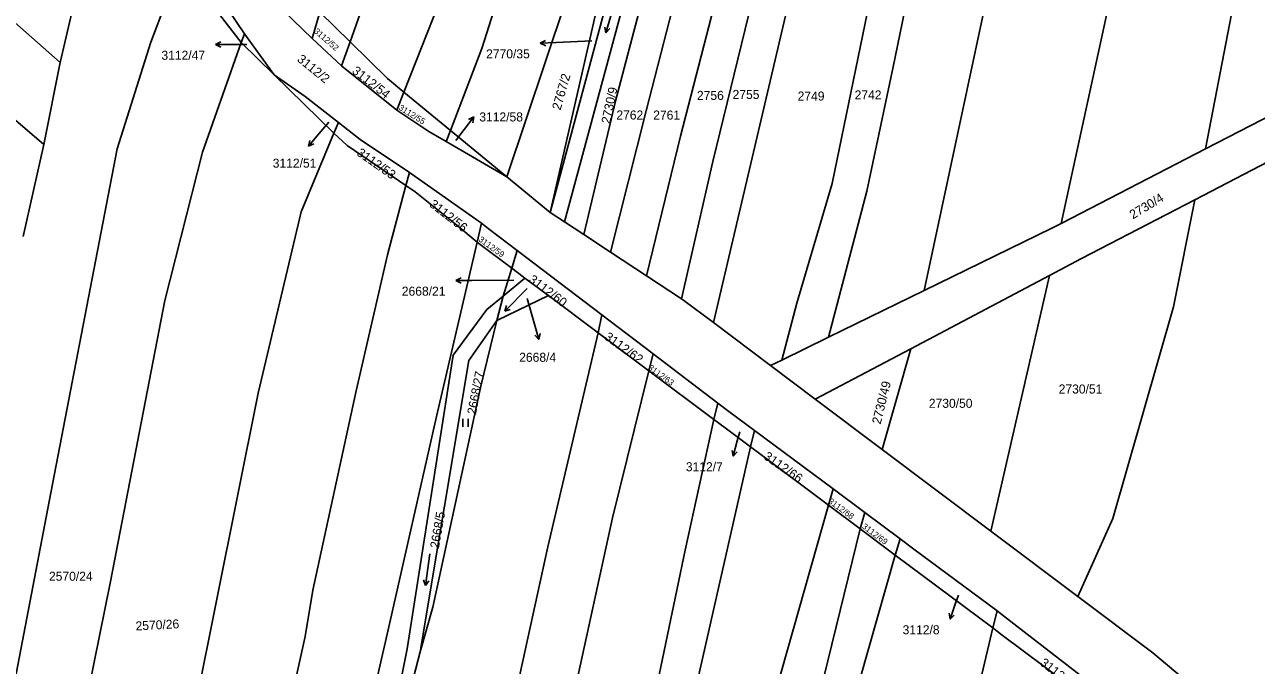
# Model space of a CAD drawing. Extents: x -776734 to -748832, y -1118122 to -976986.
# Drawn here: x -753866 to -753634.1, y -1115185.5 to -1115064.9 of the extents above; entities that cross this region are included whole.
import ezdxf

# ---------------------------------------------------------------- set-up
doc = ezdxf.new("R2010")
doc.units = 0
for name, color, linetype in [('KM_Hranice parcel', 7, 'Continuous'), ('KM_Parcelní čísla', 7, 'Continuous'), ('KM_Pop  PČ popisy', 7, 'Continuous'), ('KM_Značky kultur', 7, 'Continuous')]:
    doc.layers.add(name, color=color, linetype=linetype)

msp = doc.modelspace()

# ---------------------------------------------------------------- linework, layer by layer
at = {"layer": 'KM_Hranice parcel'}
for p, q in [((-753835.51, -1115050.38), (-753824.6, -1115066.64)), ((-753859.25, -1115072.07), (-753855.1, -1115054.13)), ((-753764.22, -1115060.84), (-753775.17, -1115093.59)), ((-753767.01, -1115100.3), (-753757.9, -1115060.21)), ((-753811.82, -1115067.51), (-753817.24, -1115062.32)), ((-753811.82, -1115067.51), (-753810.37, -1115062.57)), ((-753810.37, -1115062.57), (-753804.69, -1115068.16)), ((-753825.23, -1115068.3), (-753824.6, -1115066.64)), ((-753824.6, -1115066.64), (-753819, -1115074.39)), ((-753806.29, -1115072.69), (-753811.82, -1115067.51)), ((-753819, -1115074.39), (-753825.23, -1115068.3)), ((-753806.29, -1115072.69), (-753804.69, -1115068.16)), ((-753607.2, -1115069.43), (-753643.69, -1115088.29)), ((-753862.33, -1115087.47), (-753859.25, -1115072.07)), ((-753807.76, -1115085.35), (-753819, -1115074.39)), ((-753795.93, -1115081), (-753806.29, -1115072.69)), ((-753645.7, -1115097.86), (-753603.38, -1115075.89)), ((-753795.93, -1115081), (-753794.59, -1115077.61)), ((-753794.59, -1115077.61), (-753785.83, -1115084.82)), ((-753807.76, -1115085.35), (-753806.88, -1115083.36)), ((-753786.63, -1115086.91), (-753785.83, -1115084.82)), ((-753785.83, -1115084.82), (-753775.17, -1115093.59)), ((-753866.24, -1115104.81), (-753862.33, -1115087.47)), ((-753775.17, -1115093.59), (-753786.63, -1115086.91)), ((-753643.69, -1115088.29), (-753670.83, -1115102.32)), ((-753794.18, -1115095.22), (-753793.53, -1115092.76)), ((-753793.53, -1115092.76), (-753779.95, -1115102.31)), ((-753792.48, -1115096.38), (-753794.18, -1115095.22)), ((-753767.01, -1115100.3), (-753775.17, -1115093.59)), ((-753784.61, -1115102.63), (-753792.48, -1115096.38)), ((-753767.01, -1115100.3), (-753764.36, -1115102.04)), ((-753780.79, -1115105.85), (-753784.61, -1115102.63)), ((-753780.79, -1115105.85), (-753779.95, -1115102.31)), ((-753760.72, -1115104.43), (-753764.36, -1115102.04)), ((-753755.69, -1115107.74), (-753760.72, -1115104.43)), ((-753780.46, -1115106.13), (-753780.79, -1115105.85)), ((-753774.28, -1115110.75), (-753780.46, -1115106.13)), ((-753774.28, -1115110.75), (-753773.27, -1115107.43)), ((-753773.27, -1115107.43), (-753757.29, -1115119.56)), ((-753748.89, -1115112.2), (-753755.69, -1115107.74)), ((-753775.87, -1115116), (-753774.28, -1115110.75)), ((-753771.78, -1115112.62), (-753775.87, -1115116)), ((-753767.37, -1115115.92), (-753771.78, -1115112.62)), ((-753742.3, -1115116.53), (-753748.89, -1115112.2)), ((-753699.18, -1115125.92), (-753673.06, -1115112.13)), ((-753684.07, -1115160.26), (-753673.06, -1115112.13)), ((-753777.06, -1115120.59), (-753767.37, -1115115.92)), ((-753775.87, -1115116), (-753777.06, -1115120.59)), ((-753758.02, -1115122.91), (-753767.37, -1115115.92)), ((-753714.63, -1115123.75), (-753696.62, -1115114.96)), ((-753758.02, -1115122.91), (-753757.29, -1115119.56)), ((-753757.29, -1115119.56), (-753747.63, -1115126.9)), ((-753725.55, -1115129.08), (-753736.31, -1115120.99)), ((-753748.44, -1115130.08), (-753758.02, -1115122.91)), ((-753714.63, -1115123.75), (-753723.41, -1115128.04)), ((-753699.18, -1115125.92), (-753717.13, -1115135.41)), ((-753704.57, -1115144.86), (-753699.18, -1115125.92)), ((-753748.44, -1115130.08), (-753747.63, -1115126.9)), ((-753747.63, -1115126.9), (-753735.47, -1115136.14)), ((-753723.41, -1115128.04), (-753725.55, -1115129.08)), ((-753736.23, -1115139.2), (-753748.44, -1115130.08)), ((-753725.55, -1115129.08), (-753717.13, -1115135.41)), ((-753735.47, -1115136.14), (-753736.23, -1115139.2)), ((-753735.47, -1115136.14), (-753733.4, -1115137.71)), ((-753704.57, -1115144.86), (-753717.13, -1115135.41)), ((-753736.23, -1115139.2), (-753734.12, -1115140.78)), ((-753733.4, -1115137.71), (-753728.55, -1115141.32)), ((-753734.12, -1115140.78), (-753729.32, -1115144.37)), ((-753729.32, -1115144.37), (-753728.55, -1115141.32)), ((-753684.07, -1115160.26), (-753704.57, -1115144.86)), ((-753714.65, -1115155.34), (-753713.79, -1115152.29)), ((-753713.79, -1115152.29), (-753707.79, -1115156.75)), ((-753708.66, -1115159.82), (-753714.65, -1115155.34)), ((-753708.66, -1115159.82), (-753707.79, -1115156.75)), ((-753707.79, -1115156.75), (-753701.17, -1115161.67)), ((-753702.08, -1115164.74), (-753708.66, -1115159.82)), ((-753667.69, -1115172.56), (-753684.07, -1115160.26)), ((-753701.17, -1115161.67), (-753702.08, -1115164.74)), ((-753701.17, -1115161.67), (-753698.57, -1115163.61)), ((-753702.08, -1115164.74), (-753699.38, -1115166.76)), ((-753698.57, -1115163.61), (-753682.93, -1115175.26)), ((-753699.38, -1115166.76), (-753683.72, -1115178.46)), ((-753683.72, -1115178.46), (-753682.93, -1115175.26)), ((-753792.82, -1115188.05), (-753791.53, -1115182.96))]:
    msp.add_line(p, q, dxfattribs=at)
for points in [[(-753794.59, -1115077.61), (-753787.93, -1115060.8), (-753777.91, -1115023.56), (-753764.5, -1114964.39), (-753747.45, -1114890.29), (-753735.04, -1114826.44), (-753725.78, -1114788.24), (-753719.01, -1114758.28), (-753706.47, -1114700.23), (-753694.32, -1114647.7), (-753687.72, -1114622.89), (-753664.72, -1114512.91)], [(-753744.88, -1114812.91), (-753755.85, -1114860.59), (-753768.37, -1114915.99), (-753784.17, -1114987.23), (-753793.11, -1115028.22), (-753799.33, -1115052.95), (-753804.69, -1115068.16)], [(-754067.98, -1114882.52), (-754045.71, -1114907.17), (-754004.24, -1114946.2), (-753952.66, -1114990.3), (-753910.37, -1115026.73), (-753875.85, -1115057.43), (-753859.25, -1115072.07)], [(-754071.13, -1114898.39), (-754049.63, -1114922.2), (-754022.66, -1114947.85), (-753952.63, -1115010.37), (-753898.79, -1115056.16), (-753862.33, -1115087.47)], [(-753785.83, -1115084.82), (-753779.91, -1115069.41), (-753771.27, -1115042.16), (-753765.37, -1115019.27), (-753758.96, -1114991.55), (-753748.31, -1114942.85)], [(-753670.83, -1115102.32), (-753662.8, -1115065.45), (-753655.03, -1115029.36), (-753643.9, -1114977.12)], [(-753619.54, -1114977.59), (-753625.43, -1114999.63), (-753637.42, -1115055.73), (-753643.69, -1115088.29)], [(-753696.62, -1115114.96), (-753683.7, -1115054.43), (-753667.69, -1114984.06)], [(-753727.25, -1115015.85), (-753732.26, -1115046.29), (-753742.51, -1115085.92), (-753748.89, -1115112.2)], [(-753730.97, -1115018.56), (-753736.42, -1115049.25), (-753741.79, -1115053.28), (-753748.97, -1115081.15), (-753755.69, -1115107.74)], [(-753764.36, -1115102.04), (-753753.61, -1115062.35), (-753744.4, -1115028.3), (-753743.32, -1115027.52)], [(-753760.72, -1115104.43), (-753754.71, -1115079.05), (-753749.42, -1115058.99), (-753743.32, -1115027.52)], [(-753699.56, -1115028.45), (-753704.22, -1115047.53), (-753713.98, -1115094.82), (-753720.64, -1115117.31), (-753723.41, -1115128.04)], [(-753693.08, -1115027.16), (-753702.48, -1115072.87), (-753707.46, -1115096.26), (-753714.63, -1115123.75)], [(-753715.37, -1115032.61), (-753722.47, -1115062.21), (-753736.31, -1115120.99)], [(-753723.63, -1115038.25), (-753736.39, -1115090.66), (-753742.3, -1115116.53)], [(-753889.22, -1115281.32), (-753884.22, -1115266.45), (-753874.89, -1115225.11), (-753861.01, -1115153.01), (-753848.53, -1115088.3), (-753842.2, -1115068.25), (-753836.55, -1115053.32)], [(-753825.23, -1115068.3), (-753834.4, -1115056.28), (-753836.55, -1115053.32)], [(-753756.2, -1115059.98), (-753756.93, -1115062.71), (-753767.01, -1115100.3)], [(-753877.5, -1115290.9), (-753872.01, -1115276.25), (-753867.16, -1115255.51), (-753849.81, -1115169.74), (-753839.59, -1115116.86), (-753832.48, -1115088.95), (-753825.23, -1115068.3)], [(-753804.69, -1115068.16), (-753797.69, -1115075.06), (-753794.59, -1115077.61)], [(-753819, -1115074.39), (-753813.17, -1115078.44), (-753806.88, -1115083.36)], [(-753786.63, -1115086.91), (-753789.87, -1115085.04), (-753795.93, -1115081)], [(-753806.88, -1115083.36), (-753802.83, -1115086.53), (-753793.53, -1115092.76)], [(-753858.9, -1115308.17), (-753841.51, -1115231.47), (-753822.03, -1115134.25), (-753813.93, -1115100.17), (-753807.76, -1115085.35)], [(-753794.18, -1115095.22), (-753805.25, -1115087.66), (-753807.76, -1115085.35)], [(-753847.38, -1115317.7), (-753839.5, -1115293.67), (-753835.79, -1115283.35), (-753829.38, -1115253.16), (-753813.14, -1115180.08), (-753811.71, -1115171.33), (-753803.55, -1115133.82), (-753797.64, -1115108.22), (-753794.18, -1115095.22)], [(-753673.06, -1115112.13), (-753667.05, -1115108.95), (-753645.7, -1115097.86)], [(-753645.7, -1115097.86), (-753649.71, -1115118.04), (-753661.1, -1115157.84), (-753667.69, -1115172.56)], [(-753779.95, -1115102.31), (-753778.72, -1115103.29), (-753773.27, -1115107.43)], [(-753670.83, -1115102.32), (-753672.59, -1115103.23), (-753696.62, -1115114.96)], [(-753835, -1115324.01), (-753823.86, -1115291.7), (-753817.46, -1115264.86), (-753807.73, -1115223.09), (-753797.54, -1115178.81), (-753788.44, -1115138.67), (-753780.79, -1115105.85)], [(-753771.78, -1115112.62), (-753772.1, -1115112.38), (-753774.28, -1115110.75)], [(-753775.87, -1115116), (-753778.95, -1115118.54), (-753785.28, -1115127.14), (-753793.95, -1115182.36), (-753795.04, -1115187.69), (-753798.54, -1115214.71)], [(-753736.31, -1115120.99), (-753741.85, -1115116.83), (-753742.3, -1115116.53)], [(-753791.53, -1115182.96), (-753782.38, -1115128.15), (-753777.06, -1115120.59)], [(-753791.53, -1115182.96), (-753789.1, -1115174.54), (-753780.09, -1115132.96), (-753777.06, -1115120.59)], [(-753758.02, -1115122.91), (-753767.5, -1115163.21), (-753775.58, -1115200.14), (-753786.55, -1115251.31), (-753798.09, -1115295.51)], [(-753789.77, -1115308.69), (-753779.04, -1115265.51), (-753765.42, -1115203.94), (-753755.29, -1115157.75), (-753748.44, -1115130.08)], [(-753776.81, -1115332.22), (-753770.23, -1115300.11), (-753762.92, -1115265.2), (-753759.22, -1115246.04), (-753751.08, -1115209.25), (-753741.66, -1115163.79), (-753736.23, -1115139.2)], [(-753728.55, -1115141.32), (-753726.86, -1115142.58), (-753713.79, -1115152.29)], [(-753773.54, -1115339.7), (-753767.38, -1115311.34), (-753760.97, -1115283.14), (-753750.71, -1115240.6), (-753738.95, -1115186.68), (-753729.32, -1115144.37)], [(-753714.65, -1115155.34), (-753727.64, -1115145.63), (-753729.32, -1115144.37)], [(-753763.66, -1115349.76), (-753755.73, -1115322.54), (-753747.14, -1115288.61), (-753733.22, -1115227.13), (-753724.6, -1115190.55), (-753714.65, -1115155.34)], [(-753759.06, -1115352.33), (-753746.83, -1115314.09), (-753739.87, -1115287.41), (-753725.63, -1115228.17), (-753718.54, -1115199.99), (-753708.66, -1115159.82)], [(-753752.14, -1115356.18), (-753741.33, -1115319.81), (-753726.82, -1115261.41), (-753708.77, -1115188.16), (-753702.08, -1115164.74)], [(-753667.69, -1115172.56), (-753653.62, -1115183.13), (-753638.63, -1115195.73), (-753623.19, -1115211.62), (-753622.14, -1115213.44)], [(-753682.93, -1115175.26), (-753681.13, -1115176.6), (-753661.17, -1115192.03)], [(-753729.17, -1115366.77), (-753720.7, -1115331.7), (-753704.97, -1115267.86), (-753693.75, -1115221.04), (-753683.72, -1115178.46)], [(-753662.43, -1115194.39), (-753681.93, -1115179.8), (-753683.72, -1115178.46)]]:
    msp.add_lwpolyline(points, dxfattribs=at)
at = {"layer": 'KM_Pop  PČ popisy'}
for p, q in [((-753768.897, -1115068.437), (-753767.923, -1115067.885)), ((-753759.18, -1115067.96), (-753765.9, -1115068.28)), ((-753830.021, -1115068.67), (-753829.02, -1115068.169)), ((-753827.02, -1115068.67), (-753830.021, -1115068.67)), ((-753830.021, -1115068.67), (-753829.02, -1115069.171)), ((-753824.13, -1115068.66), (-753827.02, -1115068.67)), ((-753765.9, -1115068.28), (-753768.897, -1115068.437)), ((-753768.897, -1115068.437), (-753767.871, -1115068.885)), ((-753808.72, -1115083.25), (-753810.61, -1115085.49)), ((-753783.21, -1115084.67), (-753781.404, -1115082.273)), ((-753781.404, -1115082.273), (-753782.407, -1115082.772)), ((-753781.404, -1115082.273), (-753781.607, -1115083.374)), ((-753810.61, -1115085.49), (-753812.539, -1115087.789)), ((-753784.8, -1115086.75), (-753783.21, -1115084.67)), ((-753812.539, -1115087.789), (-753812.279, -1115086.7)), ((-753812.539, -1115087.789), (-753811.512, -1115087.344)), ((-753784.771, -1115113.06), (-753783.77, -1115112.559)), ((-753781.77, -1115113.06), (-753784.771, -1115113.06)), ((-753784.771, -1115113.06), (-753783.77, -1115113.561)), ((-753773.88, -1115113.01), (-753781.77, -1115113.06)), ((-753771.37, -1115116.47), (-753769.97, -1115121.29)), ((-753769.97, -1115121.29), (-753769.143, -1115124.175)), ((-753769.143, -1115124.175), (-753769.9, -1115123.35)), ((-753769.143, -1115124.175), (-753768.938, -1115123.074)), ((-753731.35, -1115141.56), (-753731.81, -1115143.23)), ((-753731.81, -1115143.23), (-753732.587, -1115146.129)), ((-753732.587, -1115146.129), (-753732.811, -1115145.032)), ((-753732.587, -1115146.129), (-753731.844, -1115145.291)), ((-753690.2, -1115172.27), (-753690.8, -1115173.97)), ((-753690.8, -1115173.97), (-753691.777, -1115176.807)), ((-753691.777, -1115176.807), (-753691.924, -1115175.698)), ((-753691.777, -1115176.807), (-753690.978, -1115176.024))]:
    msp.add_line(p, q, dxfattribs=at)
at = {"layer": 'KM_Značky kultur'}
for p, q in [((-753754.896, -1115060.69), (-753756.55, -1115066.458)), ((-753756.55, -1115066.458), (-753756.763, -1115065.38)), ((-753756.55, -1115066.458), (-753755.799, -1115065.657)), ((-753771.347, -1115114.595), (-753775.589, -1115118.837)), ((-753775.589, -1115118.837), (-753775.253, -1115117.792)), ((-753775.589, -1115118.837), (-753774.544, -1115118.501)), ((-753783.481, -1115140.61), (-753783.481, -1115139.11)), ((-753782.48, -1115140.61), (-753782.48, -1115139.11)), ((-753789.663, -1115164.515), (-753790.498, -1115170.457)), ((-753790.498, -1115170.457), (-753790.859, -1115169.419)), ((-753790.498, -1115170.457), (-753789.866, -1115169.559))]:
    msp.add_line(p, q, dxfattribs=at)

# ---------------------------------------------------------------- texts
at = {"layer": 'KM_Parcelní čísla'}
for s, height, rotation, p in [('3112/52', 1.14, 319, (-753811.6, -1115066.327)), ('3112/2', 1.7, 321, (-753814.804, -1115071.69)), ('3112/54', 1.7, 321.999997, (-753804.483, -1115073.919)), ('2767/2', 1.7, 74, (-753765.102, -1115081.114)), ('2730/9', 1.7, 78, (-753755.788, -1115083.676)), ('3112/55', 1.14, 328, (-753795.666, -1115080.849)), ('3112/53', 1.7, 325, (-753803.587, -1115089.396)), ('3112/56', 1.7, 321.999997, (-753789.913, -1115099.009)), ('2730/4', 1.7, 31, (-753657.342, -1115101.578)), ('3112/59', 1.14, 324, (-753780.628, -1115105.579)), ('3112/60', 1.7, 323, (-753771.241, -1115113.198)), ('3112/62', 1.7, 324, (-753756.969, -1115124.007)), ('2668/27', 1.7, 79, (-753781.025, -1115138.412)), ('3112/63', 1.14, 324, (-753748.708, -1115129.709)), ('2730/49', 1.7, 76, (-753704.855, -1115140.225)), ('3112/66', 1.7, 325, (-753727.003, -1115146.519)), ('3112/68', 1.14, 324, (-753714.818, -1115154.849)), ('2668/5', 1.7, 80, (-753787.992, -1115163.577)), ('3112/69', 1.14, 323, (-753708.444, -1115159.57)), ('2570/26', 1.7, 3, (-753845.035, -1115178.938)), ('3112/71', 1.7, 321.999997, (-753674.983, -1115185.299))]:
    msp.add_text(s, height=height, rotation=rotation, dxfattribs=at).set_placement(p)
for s, p in [('3112/47', (-753840.213, -1115071.538)), ('2770/35', (-753779.093, -1115071.268)), ('2755', (-753732.7, -1115078.91)), ('2756', (-753739.41, -1115079.09)), ('2749', (-753720.46, -1115079.21)), ('2742', (-753709.73, -1115078.99)), ('3112/58', (-753780.38, -1115083.14)), ('2762', (-753754.58, -1115082.78)), ('2761', (-753747.64, -1115082.79)), ('3112/51', (-753819.263, -1115091.838)), ('2668/21', (-753794.963, -1115115.928)), ('2668/4', (-753772.87, -1115128.368)), ('2730/51', (-753671.32, -1115134.34)), ('2730/50', (-753695.76, -1115137.03)), ('3112/7', (-753741.505, -1115148.968)), ('2570/24', (-753861.38, -1115169.57)), ('3112/8', (-753700.695, -1115179.648))]:
    msp.add_text(s, height=1.7, dxfattribs=at).set_placement(p)

doc.saveas('drawing.dxf')
